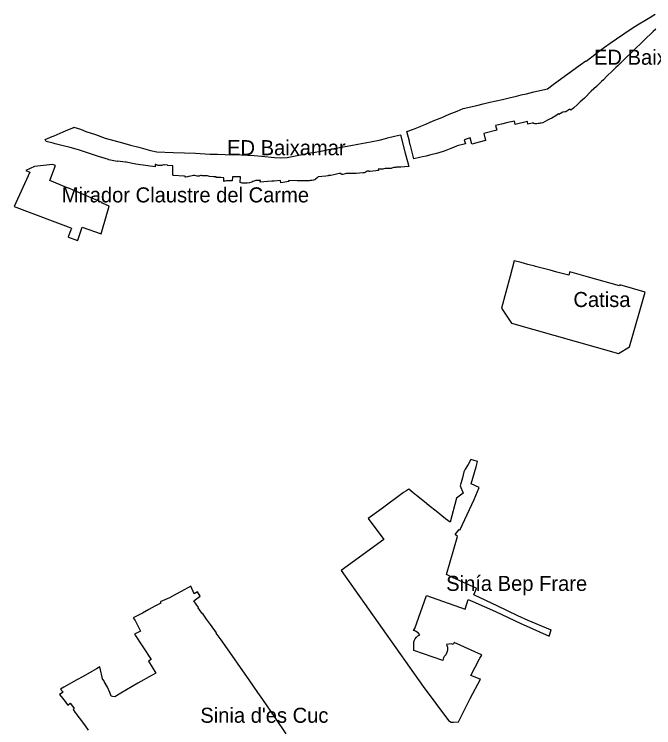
# Model space of a CAD drawing. Extents: x 599912 to 613490, y 4411003 to 4422920.
# Drawn here: x 608282 to 608792, y 4415809 to 4416377 of the extents above; entities that cross this region are included whole.
import ezdxf

# ---------------------------------------------------------------- set-up
doc = ezdxf.new("R2010")
doc.units = 0
for name, color, linetype in [('Estudi de Detall', 7, 'Continuous'), ('Pla Especial de Reforma Interior', 7, 'Continuous'), ('Sector amb disposicions transitòries', 7, 'Continuous'), ("Unitat d'Actuació", 7, 'Continuous')]:
    doc.layers.add(name, color=color, linetype=linetype)

msp = doc.modelspace()

# ---------------------------------------------------------------- linework, layer by layer
at = {"layer": 'Estudi de Detall'}
msp.add_lwpolyline([(608793.4, 4416365.43), (608791.28, 4416363.64), (608790.5, 4416362.99), (608788.85, 4416361.43), (608786.61, 4416359.31), (608785.2, 4416357.92), (608783.35, 4416356.1), (608782.45, 4416355.21), (608776.42, 4416349.28), (608767.33, 4416340.53), (608763.26, 4416336.62), (608761.49, 4416334.91), (608758.8, 4416332.3), (608754.47, 4416328.09), (608751.59, 4416325.29), (608750.13, 4416323.89), (608746.06, 4416319.97), (608742, 4416316.06), (608736.48, 4416310.64), (608733.19, 4416307.66), (608731.79, 4416306.35), (608730.7, 4416305.3), (608728.33, 4416303.09), (608727.8, 4416302.63), (608726.82, 4416301.87), (608725.92, 4416301.24), (608725.59, 4416301.03), (608724.99, 4416301.8), (608721.56, 4416299.72), (608720.94, 4416299.64), (608719.18, 4416299.42), (608716.13, 4416297.54), (608715.71, 4416298.15), (608713.72, 4416296.53), (608710.41, 4416294.72), (608708.78, 4416293.83), (608707.2, 4416293.06), (608703.24, 4416291.02), (608701.97, 4416290.71), (608701.35, 4416290.57), (608700.46, 4416290.41), (608699.57, 4416290.29), (608698.68, 4416290.22), (608697.78, 4416290.19), (608696.88, 4416290.21), (608695.99, 4416290.27), (608695.8, 4416291.03), (608691.32, 4416289.79), (608691.07, 4416291.91), (608681.41, 4416289.63), (608680.81, 4416292.31), (608675.33, 4416291.07), (608670.46, 4416289.97), (608665.68, 4416288.89), (608666.69, 4416285.18), (608656.33, 4416282.45), (608657.76, 4416276.78), (608652.58, 4416275.48), (608646.69, 4416274), (608645.52, 4416278.87), (608640.77, 4416277.29), (608641.59, 4416274.26), (608635.05, 4416272.64), (608632.11, 4416271.37), (608630.11, 4416270.51), (608624.83, 4416268.23), (608624.02, 4416267.99), (608618.69, 4416266.47), (608613.12, 4416265.08), (608610.34, 4416264.48), (608607.5, 4416263.86), (608605.09, 4416263.32), (608600.5, 4416262.3), (608599.33, 4416267.44), (608597.88, 4416272.84), (608597.75, 4416273.34), (608597.11, 4416275.73), (608596.97, 4416276.23), (608594.91, 4416283.94), (608600.15, 4416285.85), (608605.61, 4416288.11), (608606.19, 4416288.35), (608610, 4416289.92), (608610.62, 4416290.18), (608616.06, 4416292.42), (608621.62, 4416294.72), (608622.34, 4416295.02), (608628.83, 4416297.7), (608635.05, 4416300.26), (608639.89, 4416302.26), (608650.7, 4416304.8), (608655.7, 4416305.98), (608661.23, 4416307.28), (608666.29, 4416308.47), (608671.17, 4416309.61), (608676.58, 4416310.88), (608682.25, 4416312.22), (608686.12, 4416313.13), (608690.21, 4416314.09), (608696.25, 4416315.51), (608707.04, 4416318.04), (608711.69, 4416321.44), (608733.22, 4416337.21), (608737.64, 4416340.33), (608737.77, 4416340.16), (608742.39, 4416343.64), (608747.54, 4416347.4), (608752.6, 4416351.09), (608757.14, 4416354.4), (608761.97, 4416357.72), (608767.79, 4416361.73), (608775.27, 4416366.87), (608775.42, 4416366.98), (608780.08, 4416369.91), (608784.62, 4416372.57), (608788.56, 4416374.98), (608792.9, 4416377.42)], dxfattribs=at)
msp.add_lwpolyline([(608313.1, 4416274.68), (608307.44, 4416276.09), (608306.83, 4416277.68), (608312.28, 4416279.99), (608313.79, 4416280.63), (608320.99, 4416283.67), (608324.8, 4416285.29), (608329.6, 4416287.32), (608329.64, 4416287.54), (608334.84, 4416285.78), (608339.18, 4416283.97), (608346.86, 4416281.5), (608354.63, 4416278.73), (608361.35, 4416276.93), (608368.28, 4416275.04), (608374.82, 4416273.24), (608381.34, 4416271.48), (608390.58, 4416268.78), (608395.8, 4416267.86), (608408.79, 4416267.25), (608417.85, 4416266.94), (608426.61, 4416266.65), (608430.16, 4416266.43), (608434.13, 4416266.19), (608437.9, 4416265.97), (608443.94, 4416265.92), (608450.2, 4416265.81), (608456.86, 4416265.42), (608456.88, 4416265.68), (608463, 4416265.36), (608468.33, 4416265.08), (608473.35, 4416264.83), (608479.16, 4416264.33), (608489.46, 4416263.32), (608494.18, 4416263.04), (608499.5, 4416263.23), (608504.8, 4416264.43), (608510.31, 4416265.46), (608515.15, 4416266.37), (608517.06, 4416266.72), (608518.25, 4416266.95), (608520.38, 4416267.34), (608526.29, 4416268.45), (608532.5, 4416269.62), (608538.44, 4416270.73), (608550.36, 4416272.96), (608555.98, 4416274.01), (608561.77, 4416275.1), (608567.45, 4416276.16), (608573.04, 4416277.21), (608579.11, 4416278.75), (608579.48, 4416278.85), (608585.15, 4416280.29), (608589.81, 4416281.48), (608593.75, 4416266.68), (608595.53, 4416259.99), (608596.57, 4416256.09), (608593.15, 4416255.78), (608593.12, 4416255.77), (608590.29, 4416255.51), (608587.79, 4416255.61), (608587.75, 4416255.61), (608586.73, 4416255.48), (608586.13, 4416255.47), (608584.84, 4416255.47), (608584.53, 4416255.42), (608584.23, 4416255.35), (608582.42, 4416254.5), (608577.6, 4416254.65), (608576.57, 4416254.23), (608575.86, 4416254.12), (608572.91, 4416254.06), (608572.19, 4416254.1), (608572.46, 4416252.84), (608565.87, 4416252.16), (608565.35, 4416252.07), (608565.08, 4416252.08), (608564.92, 4416252.13), (608564.86, 4416252.18), (608564.6, 4416252.48), (608564.5, 4416252.51), (608564.24, 4416252.52), (608563.47, 4416252.39), (608563.21, 4416252.29), (608562.56, 4416251.99), (608561.7, 4416251.42), (608561.16, 4416251.2), (608560.56, 4416251.07), (608560.27, 4416251.06), (608559.86, 4416251.06), (608554.69, 4416250.58), (608554.11, 4416250.53), (608552.89, 4416250.52), (608551.64, 4416250.55), (608549.89, 4416250.66), (608548.4, 4416250.69), (608547.21, 4416250.68), (608546.62, 4416250.59), (608545.85, 4416250.37), (608544.02, 4416249.74), (608543.58, 4416249.64), (608543.24, 4416249.64), (608543.13, 4416249.66), (608543.02, 4416249.73), (608542.94, 4416249.84), (608542.82, 4416250.06), (608542.64, 4416250.29), (608542.48, 4416250.39), (608542.28, 4416250.44), (608541.77, 4416250.54), (608541.05, 4416250.51), (608538.87, 4416250.1), (608536.76, 4416249.61), (608534.31, 4416249.05), (608533.64, 4416248.96), (608532.66, 4416248.88), (608532.3, 4416248.82), (608532.05, 4416248.74), (608530.32, 4416248.53), (608524.31, 4416247.78), (608523.4, 4416247.02), (608522.18, 4416245.93), (608521.8, 4416245.67), (608521.68, 4416245.6), (608521.47, 4416245.5), (608520.51, 4416245.25), (608519.38, 4416245.04), (608518.81, 4416244.97), (608518, 4416244.89), (608517.01, 4416244.84), (608514.03, 4416244.72), (608513.13, 4416244.68), (608507.43, 4416244.71), (608500.76, 4416244.99), (608500.83, 4416244.06), (608494.45, 4416243.23), (608494.39, 4416244.93), (608489.32, 4416244.55), (608487.42, 4416244.57), (608484.22, 4416244.22), (608483.91, 4416244.19), (608478.18, 4416243.57), (608478.26, 4416244.87), (608477.29, 4416245.11), (608474.66, 4416244.93), (608472.9, 4416244.36), (608472.27, 4416244.06), (608471.41, 4416243.64), (608469.59, 4416243.1), (608467.82, 4416242.84), (608467.72, 4416242.84), (608467.18, 4416242.81), (608463.79, 4416242.73), (608462.22, 4416243.36), (608462.22, 4416243.76), (608462.38, 4416247.83), (608455.94, 4416247.9), (608455.77, 4416244.81), (608452.81, 4416244.67), (608451.11, 4416244.61), (608450.3, 4416244.52), (608449.51, 4416244.38), (608449.04, 4416244.3), (608449.19, 4416246.99), (608449.2, 4416247.12), (608449.07, 4416247.12), (608446.76, 4416247.25), (608443.01, 4416247.45), (608443.03, 4416247.88), (608440.77, 4416248), (608437.61, 4416248.22), (608436.01, 4416248.75), (608435.5, 4416248.71), (608433.75, 4416248.73), (608432.68, 4416248.58), (608432.54, 4416248.6), (608432.23, 4416248.66), (608431.28, 4416248.95), (608431.06, 4416248.96), (608430.84, 4416248.91), (608429.88, 4416248.58), (608429.54, 4416248.52), (608428.58, 4416248.42), (608428.35, 4416248.43), (608427.95, 4416248.47), (608426.03, 4416248.85), (608425.47, 4416248.96), (608425.2, 4416248.99), (608424.88, 4416248.99), (608421.47, 4416248.11), (608421.01, 4416248.04), (608420.13, 4416247.99), (608418.43, 4416247.67), (608418.48, 4416248.18), (608417.89, 4416248.36), (608417.11, 4416248.41), (608408.94, 4416249.03), (608408.38, 4416249.12), (608408.51, 4416253.84), (608408.57, 4416256.79), (608404.45, 4416257.06), (608404.34, 4416257.08), (608401.67, 4416257.54), (608400.98, 4416257.49), (608399.7, 4416257.03), (608398.83, 4416256.95), (608397.06, 4416256.87), (608396.4, 4416257.04), (608395.52, 4416257.42), (608394.91, 4416257.68), (608394.42, 4416257.72), (608394.26, 4416255.74), (608388.54, 4416256.63), (608379.06, 4416258.1), (608376.42, 4416258.52), (608372.68, 4416259.26), (608372.61, 4416259.27), (608371.23, 4416259.54), (608370.66, 4416259.66), (608368.51, 4416259.77), (608364.27, 4416260.5), (608364.14, 4416260.05), (608357.59, 4416261.53), (608357.25, 4416261.64), (608349.25, 4416264.2), (608341.37, 4416266.72), (608334.16, 4416269.08), (608329.61, 4416270.47), (608326.63, 4416271.38), (608321.15, 4416272.72), (608314.62, 4416274.31)], close=True, dxfattribs=at)
at = {"layer": 'Pla Especial de Reforma Interior'}
msp.add_lwpolyline([(608636.06, 4415813.65), (608645.34, 4415832.15), (608653.71, 4415847.65), (608653.34, 4415847.79), (608646.03, 4415850.6), (608646.07, 4415850.68), (608653, 4415863.86), (608653.27, 4415864.43), (608654.82, 4415866.83), (608654.46, 4415867), (608632.56, 4415876.95), (608632, 4415875.27), (608630.19, 4415875.74), (608626.47, 4415875.25), (608627.27, 4415873.15), (608627.33, 4415870.92), (608627.1, 4415869.82), (608626.02, 4415867.08), (608624.67, 4415865.74), (608624.2, 4415864.72), (608623.58, 4415862.5), (608600.62, 4415870.39), (608600.49, 4415875.68), (608600.64, 4415877.37), (608600.86, 4415878.19), (608601.54, 4415879.74), (608602.63, 4415881.17), (608603.84, 4415882.2), (608605.34, 4415883), (608604.02, 4415884.66), (608601.75, 4415886.02), (608600.38, 4415886.56), (608601.37, 4415888.07), (608610.63, 4415914.45), (608641.35, 4415903.34), (608643.94, 4415911.13), (608647.55, 4415909.55), (608665.67, 4415901.58), (608685.75, 4415892.1), (608687.58, 4415891.24), (608708.49, 4415882.06), (608709.89, 4415886.9), (608709.54, 4415887.04), (608691.61, 4415894.39), (608683.53, 4415898.04), (608666.88, 4415906.13), (608662.9, 4415908.06), (608657.89, 4415910.42), (608648.42, 4415914.89), (608648.44, 4415914.94), (608650.6, 4415919.93), (608650.25, 4415920.09), (608631.49, 4415928.55), (608626.51, 4415931.03), (608626.52, 4415931.08), (608635.37, 4415961.48), (608633.58, 4415962.91), (608636.68, 4415966.9), (608636.71, 4415966.93), (608636.95, 4415966.73), (608637.26, 4415966.48), (608637.48, 4415966.94), (608648.5, 4415990.9), (608652.7, 4416000.36), (608646.35, 4416003.18), (608650.25, 4416016.98), (608651.39, 4416021.01), (608647.78, 4416022.07), (608645.88, 4416022.63), (608643.78, 4416018.74), (608641.46, 4416015.07), (608640.41, 4416012.96), (608639.25, 4416008.07), (608637.43, 4416001.6), (608639.89, 4415995.75), (608634.42, 4415991.76), (608629.4, 4415972.7), (608625.89, 4415975.46), (608618.31, 4415981.51), (608612.89, 4415985.84), (608610.52, 4415987.73), (608606.5, 4415990.99), (608602.73, 4415994.04), (608600.06, 4415996.21), (608596.63, 4415999.18), (608594.16, 4415997.48), (608592.43, 4415996.28), (608574.41, 4415983.14), (608564.21, 4415975.7), (608576.61, 4415958.91), (608542.75, 4415934.34), (608607.99, 4415841.72), (608628.2, 4415814.88), (608630.19, 4415813.54), (608632.23, 4415813.36)], close=True, dxfattribs=at)
at = {"layer": 'Sector amb disposicions transitòries'}
msp.add_lwpolyline([(608724.91, 4416172.32), (608724.17, 4416169.52), (608714.41, 4416172.08), (608709.12, 4416173.48), (608697.51, 4416176.53), (608697.03, 4416176.66), (608691.46, 4416178.12), (608686.19, 4416179.57), (608680.58, 4416181.05), (608677.26, 4416168.63), (608670.46, 4416143.16), (608678.36, 4416131.35), (608763.54, 4416107.28), (608772.54, 4416112.44), (608784.97, 4416155.95), (608764.77, 4416161.8), (608764.52, 4416160.94), (608739.79, 4416168.04)], close=True, dxfattribs=at)
at = {"layer": "Unitat d'Actuació"}
msp.add_lwpolyline([(608312.54, 4416257.79), (608298.24, 4416256.18), (608291.18, 4416252.85), (608294.43, 4416251.69), (608282.09, 4416224.17), (608314.39, 4416212.01), (608325.04, 4416207.98), (608327.72, 4416206.97), (608327.69, 4416206.9), (608326.96, 4416205), (608325.09, 4416200.07), (608325.43, 4416199.94), (608332.6, 4416197.25), (608332.69, 4416197.51), (608336.18, 4416207.75), (608351.47, 4416202.49), (608352.54, 4416206.22), (608357.8, 4416224.51), (608357.82, 4416224.57), (608352.34, 4416226.84), (608351.99, 4416226.98), (608352.15, 4416227.37), (608351.89, 4416227.55), (608348.4, 4416229.03), (608343.5, 4416231.09), (608328.52, 4416237.48), (608325.99, 4416238.55), (608323.77, 4416239.5), (608310.38, 4416245.11), (608315.04, 4416256.8)], close=True, dxfattribs=at)
msp.add_lwpolyline([(608498.83, 4415804.15), (608489.93, 4415817.25), (608480.18, 4415831.43), (608476.23, 4415837.11), (608469.26, 4415847.11), (608462.3, 4415857.02), (608455.69, 4415866.54), (608447.06, 4415878.91), (608443.04, 4415884.38), (608443.33, 4415884.59), (608438.58, 4415891.25), (608435.38, 4415895.37), (608432.18, 4415900.14), (608431.77, 4415900.03), (608428.65, 4415904.51), (608429, 4415904.75), (608425.28, 4415910.05), (608430.3, 4415913.82), (608428.16, 4415917.21), (608425.53, 4415915.7), (608422.92, 4415921.79), (608414.98, 4415917.65), (608410.67, 4415915.06), (608405.81, 4415912.52), (608398.33, 4415909.18), (608398.86, 4415908.13), (608394.14, 4415905.74), (608389.43, 4415903.12), (608384.25, 4415900.3), (608376.98, 4415896.56), (608378.47, 4415894.32), (608382.65, 4415885.91), (608377.99, 4415883.5), (608391.18, 4415863.39), (608389.03, 4415861.98), (608394.92, 4415852.53), (608391.9, 4415850.75), (608380.63, 4415844.44), (608367.07, 4415836.4), (608362.17, 4415833.5), (608360.36, 4415833.74), (608359.45, 4415834.04), (608358.13, 4415836.95), (608356.27, 4415841.2), (608353.72, 4415845.85), (608353.34, 4415847.05), (608352.7, 4415846.99), (608350.34, 4415857.38), (608347.67, 4415855.86), (608343.82, 4415853.69), (608336.95, 4415849.79), (608331.98, 4415847.14), (608321.48, 4415841.19), (608319.05, 4415839.8), (608320.94, 4415837.39), (608318.27, 4415835.37), (608320.46, 4415832.43), (608321.48, 4415831.24), (608322.57, 4415829.78), (608323.63, 4415828.35), (608324.69, 4415826.94), (608326.75, 4415828.61), (608328.51, 4415826.17), (608329.93, 4415824.25), (608329.01, 4415823.51), (608330.47, 4415821.51), (608331.67, 4415819.88), (608332.77, 4415818.32), (608334.76, 4415815.64), (608338.48, 4415810.58), (608341.06, 4415807.12)], dxfattribs=at)

# ---------------------------------------------------------------- texts
at = {"layer": 'Estudi de Detall'}
for p in [(608744.13, 4416337.19), (608451.7, 4416265.13)]:
    msp.add_text('ED Baixamar', height=12, dxfattribs=at).set_placement(p)
at = {"layer": 'Pla Especial de Reforma Interior'}
msp.add_text('Sinía Bep Frare', height=12, dxfattribs=at).set_placement((608626.32, 4415917.99))
at = {"layer": 'Sector amb disposicions transitòries'}
msp.add_text('Catisa', height=12, dxfattribs=at).set_placement((608727.72, 4416144.17))
at = {"layer": "Unitat d'Actuació"}
for s, p in [('Mirador Claustre del Carme', (608319.96, 4416227.52)), ("Sinia d'es Cuc", (608430.4, 4415812.93))]:
    msp.add_text(s, height=12, dxfattribs=at).set_placement(p)

doc.saveas('drawing.dxf')
